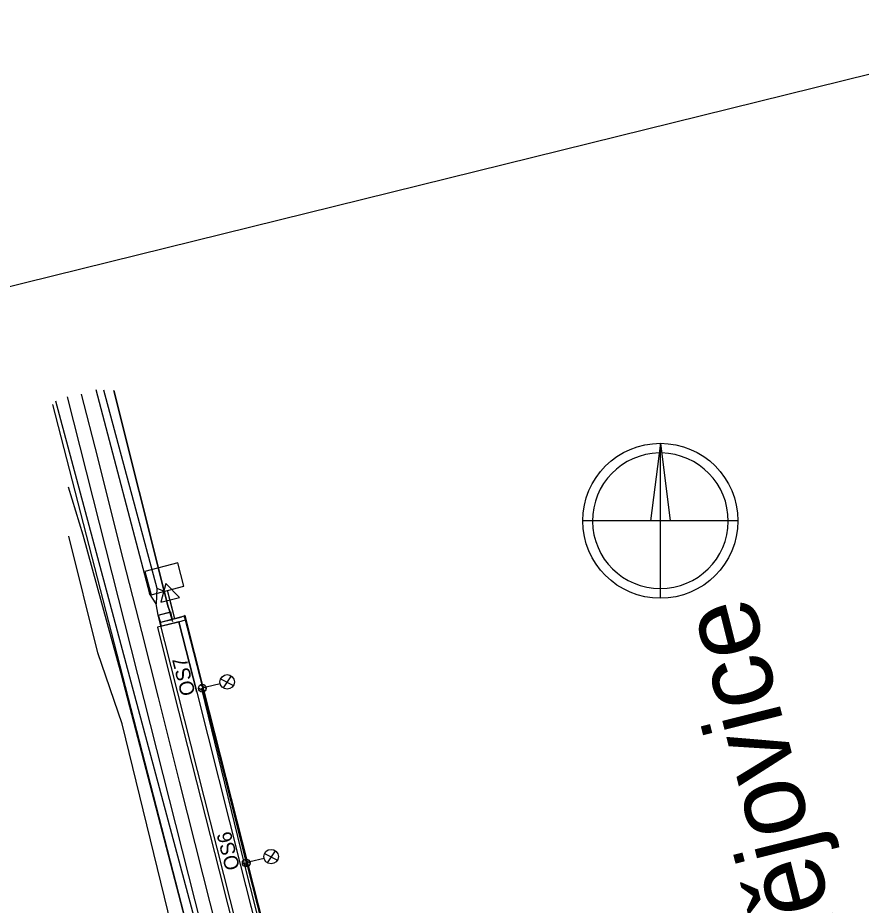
# Model space of a CAD drawing. Extents: x -754679 to -754173, y -1169241 to -1168288.
# Drawn here: x -754428.7 to -754341.7, y -1168864.2 to -1168772.6 of the extents above; entities that cross this region are included whole.
import ezdxf

# ---------------------------------------------------------------- set-up
doc = ezdxf.new("R2010")
doc.units = 0
for name, color, linetype in [('Vrstva 1', 7, 'Continuous'), ('Vrstva 13', 7, 'Continuous'), ('Vrstva 14', 7, 'Continuous'), ('Vrstva 16', 7, 'Continuous'), ('Vrstva 17', 7, 'Continuous'), ('Vrstva 23', 7, 'Continuous'), ('Vrstva 25', 7, 'Continuous'), ('Vrstva 4', 7, 'Continuous'), ('Vrstva 51', 7, 'Continuous'), ('Vrstva 61', 7, 'Continuous'), ('Vrstva 7', 7, 'Continuous')]:
    doc.layers.add(name, color=color, linetype=linetype)

msp = doc.modelspace()

# ---------------------------------------------------------------- linework, layer by layer
at = {"layer": 'Vrstva 1'}
for p, q in [((-754362.388, -1168816.492), (-754363.388, -1168824.492)), ((-754362.388, -1168832.492), (-754362.388, -1168816.492)), ((-754354.388, -1168824.492), (-754370.388, -1168824.492))]:
    msp.add_line(p, q, dxfattribs=at)
msp.add_lwpolyline([(-754398.294, -1168905.574), (-754400.74, -1168895.891), (-754402.939, -1168887.198), (-754405.133, -1168878.507), (-754407.339, -1168869.778), (-754409.539, -1168861.07), (-754411.979, -1168851.401), (-754414.173, -1168842.726), (-754415.893, -1168835.935), (-754418.063, -1168827.345), (-754420.434, -1168817.966), (-754422.091, -1168811.412)], dxfattribs=at)
msp.add_lwpolyline([(-754362.388, -1168816.492), (-754361.388, -1168824.492), (-754362.388, -1168824.492)], close=True, dxfattribs=at)
msp.add_circle((-754362.388, -1168824.492), 8, dxfattribs=at)
msp.add_arc((-754362.388, -1168824.492), 7, 91.02434, 88.97566, dxfattribs=at)
at = {"layer": 'Vrstva 13'}
for points in [[(-754411.382, -1168834.702), (-754411.508, -1168834.326), (-754413.963, -1168834.996)], [(-754413.963, -1168834.996), (-754413.919, -1168835.387), (-754412.047, -1168834.907), (-754411.382, -1168834.702)]]:
    msp.add_lwpolyline(points, dxfattribs=at)
at = {"layer": 'Vrstva 14'}
for p, q in [((-754412.047, -1168834.907), (-754414.276, -1168835.483)), ((-754410.208, -1168842.187), (-754412.047, -1168834.907)), ((-754410.208, -1168842.187), (-754405.698, -1168860.083)), ((-754405.698, -1168860.083), (-754401.304, -1168877.422))]:
    msp.add_line(p, q, dxfattribs=at)
msp.add_lwpolyline([(-754414.276, -1168835.483), (-754412.566, -1168842.248), (-754407.917, -1168860.63), (-754403.513, -1168878.067), (-754399.115, -1168895.474), (-754395.207, -1168910.943), (-754391.772, -1168924.511), (-754387.375, -1168941.909)], dxfattribs=at)
at = {"layer": 'Vrstva 16'}
for p, q in [((-754420.431, -1168838.11), (-754423.4, -1168826.097)), ((-754417.897, -1168845.451), (-754420.431, -1168838.11)), ((-754412.329, -1168868.322), (-754417.897, -1168845.451))]:
    msp.add_line(p, q, dxfattribs=at)
msp.add_lwpolyline([(-754410.781, -1168867.993), (-754417.976, -1168840.388), (-754421.932, -1168825.961), (-754423.457, -1168821.011)], dxfattribs=at)
at = {"layer": 'Vrstva 17'}
msp.add_lwpolyline([(-754413.066, -1168833.719), (-754412.781, -1168834.716), (-754412.781, -1168834.719), (-754412.717, -1168834.897)], dxfattribs=at)
at = {"layer": 'Vrstva 23'}
msp.add_lwpolyline([(-754418.777, -1168811.03), (-754413.585, -1168831.745), (-754413.172, -1168833.378), (-754412.965, -1168833.919)], dxfattribs=at)
at = {"layer": 'Vrstva 25'}
for p, q in [((-754407.801, -1168841.309), (-754409.255, -1168841.677)), ((-754407.747, -1168840.801), (-754406.419, -1168841.48)), ((-754406.655, -1168840.51), (-754407.489, -1168841.746)), ((-754410.038, -1168841.75), (-754409.431, -1168842.112)), ((-754409.816, -1168841.417), (-754409.246, -1168841.757)), ((-754402.122, -1168858.546), (-754402.957, -1168859.782)), ((-754405.284, -1168859.452), (-754404.714, -1168859.792)), ((-754403.269, -1168859.345), (-754404.723, -1168859.712)), ((-754403.214, -1168858.837), (-754401.887, -1168859.517)), ((-754405.506, -1168859.785), (-754404.899, -1168860.147))]:
    msp.add_line(p, q, dxfattribs=at)
for points in [[(-754409.643, -1168841.775), (-754409.73, -1168841.84), (-754405.311, -1168859.885), (-754405.111, -1168859.81)], [(-754405.311, -1168859.885), (-754400.951, -1168877.139), (-754400.72, -1168877.056)]]:
    msp.add_lwpolyline(points, dxfattribs=at)
for centre, radius in [((-754407.076, -1168841.123), 0.749), ((-754409.643, -1168841.775), 0.4), ((-754402.544, -1168859.159), 0.749), ((-754405.111, -1168859.81), 0.4)]:
    msp.add_circle(centre, radius, dxfattribs=at)
at = {"layer": 'Vrstva 4'}
for p, q in [((-754420.63, -1168810.942), (-754415.086, -1168831.992)), ((-754419.828, -1168810.988), (-754414.324, -1168831.462)), ((-754413.585, -1168831.745), (-754418.777, -1168811.03)), ((-754423.571, -1168811.713), (-754409.415, -1168867.665)), ((-754425.102, -1168812.48), (-754410.781, -1168867.993)), ((-754409.837, -1168867.801), (-754424.763, -1168812.141)), ((-754414.324, -1168831.462), (-754414.393, -1168833.05)), ((-754414.324, -1168831.462), (-754413.585, -1168831.745)), ((-754413.172, -1168833.378), (-754413.585, -1168831.745)), ((-754405.916, -1168866.884), (-754414.18, -1168834.25))]:
    msp.add_line(p, q, dxfattribs=at)
for points in [[(-754414.18, -1168834.25), (-754414.393, -1168833.05), (-754415.086, -1168831.992)], [(-754414.18, -1168834.25), (-754412.965, -1168833.919), (-754413.172, -1168833.378)]]:
    msp.add_lwpolyline(points, dxfattribs=at)
at = {"layer": 'Vrstva 51'}
for p, q in [((-754414.198, -1168834.247), (-754412.925, -1168833.9)), ((-754414.198, -1168834.247), (-754413.963, -1168834.996)), ((-754412.96, -1168834.718), (-754411.99, -1168834.474)), ((-754412.047, -1168834.907), (-754411.382, -1168834.702)), ((-754411.397, -1168834.286), (-754411.508, -1168834.326)), ((-754411.508, -1168834.326), (-754409.566, -1168841.96)), ((-754409.488, -1168841.918), (-754411.397, -1168834.286)), ((-754405.058, -1168859.927), (-754409.566, -1168841.96)), ((-754404.921, -1168859.923), (-754409.488, -1168841.918)), ((-754405.058, -1168859.927), (-754400.625, -1168877.238)), ((-754400.518, -1168877.236), (-754404.921, -1168859.923))]:
    msp.add_line(p, q, dxfattribs=at)
for points in [[(-754412.475, -1168834.596), (-754412.963, -1168832.656), (-754411.993, -1168832.412), (-754413.39, -1168830.959), (-754413.933, -1168832.901), (-754412.963, -1168832.656)], [(-754412.925, -1168833.9), (-754412.761, -1168834.703), (-754413.963, -1168834.996)], [(-754412.047, -1168834.907), (-754410.208, -1168842.187), (-754405.698, -1168860.083), (-754401.304, -1168877.422), (-754396.888, -1168895.004), (-754392.927, -1168910.532), (-754392.287, -1168913.272), (-754393.063, -1168913.475), (-754391.113, -1168921.242), (-754390.299, -1168921.015), (-754389.528, -1168924.038), (-754385.162, -1168941.315)]]:
    msp.add_lwpolyline(points, dxfattribs=at)
at = {"layer": 'Vrstva 61'}
msp.add_lwpolyline([(-754461.146, -1169240.796), (-754172.83, -1169169.5), (-754273.652, -1168761.781), (-754561.968, -1168833.076)], dxfattribs=at)
at = {"layer": 'Vrstva 7'}
msp.add_line((-754413.201, -1168834.785), (-754411.749, -1168834.407), dxfattribs=at)
msp.add_lwpolyline([(-754412.475, -1168834.596), (-754413.231, -1168831.693), (-754411.537, -1168831.252), (-754412.167, -1168828.833), (-754415.554, -1168829.714), (-754414.924, -1168832.133), (-754413.231, -1168831.693)], dxfattribs=at)

# ---------------------------------------------------------------- texts
at = {"layer": 'Vrstva 23'}
msp.add_text('zast. Nové Hodějovice', height=8, rotation=104.17859, dxfattribs=at).set_placement((-754326.915, -1168935.19))
at = {"layer": 'Vrstva 25'}
for s, rotation, p in [('OS7', 104.19309, (-754410.333, -1168842.343)), ('OS6', 104.17859, (-754405.743, -1168860.348))]:
    msp.add_text(s, height=1.5, rotation=rotation, dxfattribs=at).set_placement(p)

doc.saveas('drawing.dxf')
